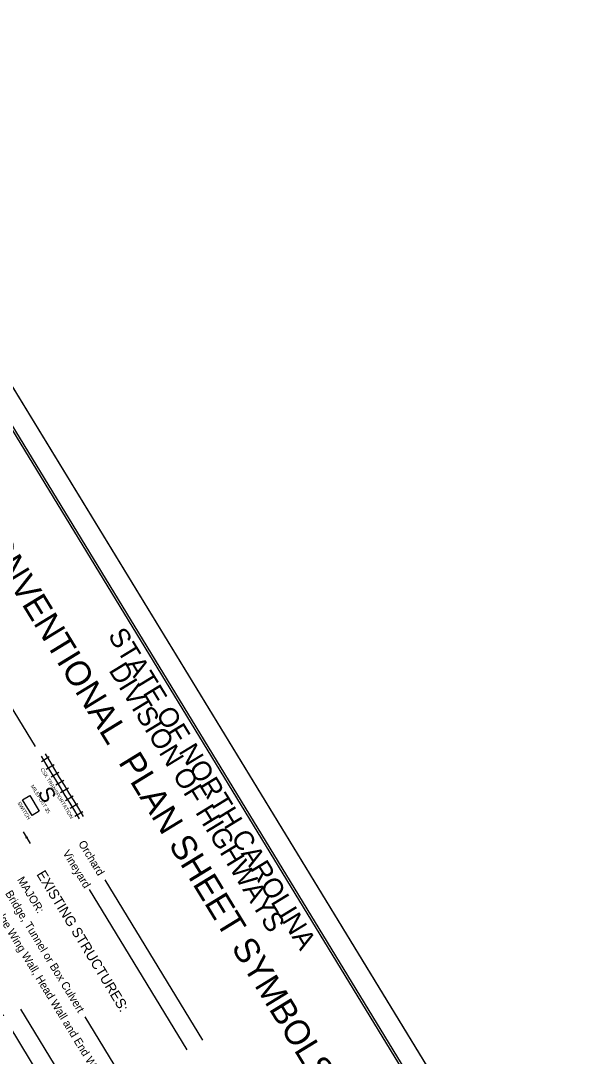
# Model space of a CAD drawing. Extents: x 1750583 to 1791140, y 783580 to 827376.
# Drawn here: x 1783107 to 1783732, y 784461 to 785591 of the extents above; entities that cross this region are included whole.
import ezdxf

# ---------------------------------------------------------------- set-up
doc = ezdxf.new("R2010")
doc.units = 0
for name, color, linetype in [('Sheet Cutting Line CELL', 7, 'Continuous'), ('Sheet Plot Border Inside CELL', 7, 'Continuous'), ('Sheet Plot Border Outside CELL', 7, 'Continuous'), ('Sheet Symbology CELL', 7, 'Continuous')]:
    doc.layers.add(name, color=color, linetype=linetype)

msp = doc.modelspace()

# ---------------------------------------------------------------- linework, layer by layer
at = {"layer": 'Sheet Cutting Line CELL'}
msp.add_line((1783731.7, 784153.6), (1782853.7, 785590.6), dxfattribs=at)
at = {"layer": 'Sheet Plot Border Inside CELL'}
msp.add_lwpolyline([(1781941, 785017.7), (1782809.9, 783595.7), (1783710.2, 784145.8), (1782841.3, 785567.8)], close=True, dxfattribs=at)
at = {"layer": 'Sheet Plot Border Outside CELL'}
msp.add_lwpolyline([(1781915.1, 785017.1), (1782793.1, 783580.1), (1783731.7, 784153.6), (1782853.7, 785590.6)], close=True, dxfattribs=at)
at = {"layer": 'Sheet Symbology CELL'}
for p, q in [((1783122.6, 784799.1), (1783040, 784934.3)), ((1783128.8, 784788.4), (1783134, 784779.9)), ((1783129.3, 784782.8), (1783137.8, 784788)), ((1783133.1, 784791), (1783138.3, 784782.5)), ((1783134, 784779.9), (1783139.2, 784771.3)), ((1783134.5, 784774.3), (1783143, 784779.5)), ((1783138.3, 784782.5), (1783143.5, 784773.9)), ((1783143.5, 784773.9), (1783148.7, 784765.4)), ((1783139.2, 784771.3), (1783144.5, 784762.8)), ((1783139.7, 784765.8), (1783148.3, 784771)), ((1783144.5, 784762.8), (1783149.7, 784754.3)), ((1783148.7, 784765.4), (1783153.9, 784756.9)), ((1783144.9, 784757.2), (1783153.5, 784762.4)), ((1783149.7, 784754.3), (1783154.9, 784745.7)), ((1783150.1, 784748.7), (1783158.7, 784753.9)), ((1783153.9, 784756.9), (1783159.2, 784748.3)), ((1783154.9, 784745.7), (1783160.1, 784737.2)), ((1783155.4, 784740.2), (1783163.9, 784745.4)), ((1783159.2, 784748.3), (1783164.4, 784739.8)), ((1783160.1, 784737.2), (1783165.3, 784728.7)), ((1783160.6, 784731.6), (1783169.1, 784736.8)), ((1783164.4, 784739.8), (1783169.6, 784731.3)), ((1783165.3, 784728.7), (1783170.5, 784720.1)), ((1783169.6, 784731.3), (1783174.8, 784722.7)), ((1783165.8, 784723.1), (1783174.3, 784728.3)), ((1783109.1, 784706), (1783116.9, 784693.2)), ((1783114.1, 784700.3), (1783111.9, 784699)), ((1783305.5, 784478.8), (1783198.6, 784653.6)), ((1783288.4, 784468.3), (1783181.6, 784643.2)), ((1783156.4, 784392.7), (1783067.7, 784538)), ((1783173.5, 784403.2), (1783106.6, 784512.7)), ((1783220.9, 784432.1), (1783176.9, 784504.2))]:
    msp.add_line(p, q, dxfattribs=at)
for points in [[(1783701.5, 784155.1), (1782919.5, 785435.1), (1782024.3, 784888.2), (1782806.4, 783608.2)], [(1783116.5, 784745.7), (1783126.9, 784728.6), (1783119.1, 784723.9), (1783108.7, 784741)]]:
    msp.add_lwpolyline(points, close=True, dxfattribs=at)

# ---------------------------------------------------------------- texts
for s, height, p in [('CONVENTIONAL  PLAN SHEET SYMBOLS', 27.2, (1783052.4, 785044.1)), ('STATE OF NORTH CAROLINA', 21.419, (1783201.3, 784920.2)), ('DIVISION OF HIGHWAYS', 21.419, (1783202.1, 784882.2)), ('CSX TRANSPORTATION', 4, (1783127.8, 784774.2)), ('MILEPOST 35', 4, (1783117.3, 784755.9)), ('S', 16.5, (1783124.6, 784748.6)), ('SWITCH', 4, (1783102.8, 784737.4)), ('Orchard', 8.75, (1783169.1, 784693.3)), ('Vineyard', 8.75, (1783152, 784682.9)), ('EXISTING STRUCTURES:', 11, (1783123.4, 784659.7)), ('MAJOR:', 8.75, (1783102.3, 784653.8)), ('Bridge, Tunnel or Box Culvert', 8.75, (1783089.3, 784638.8)), ('Bridge Wing Wall, Head Wall and End Wall', 8.75, (1783072.2, 784628.4))]:
    msp.add_text(s, height=height, rotation=301.4249, dxfattribs=at).set_placement(p)

doc.saveas('drawing.dxf')
